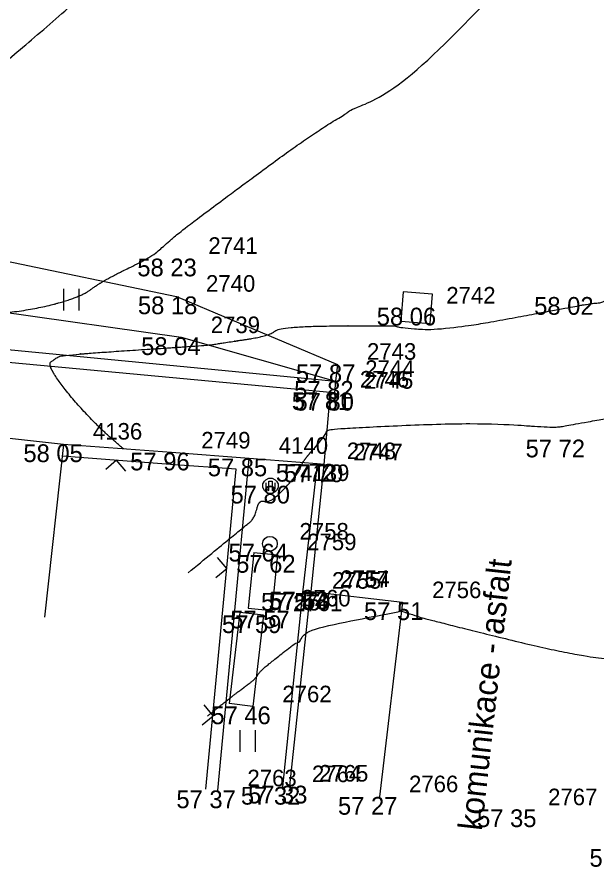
# Model space of a CAD drawing. Extents: x -704017 to -701500, y -1008977 to -1008450.
# Drawn here: x -702511.97 to -702502.17, y -1008779.72 to -1008765.36 of the extents above; entities that cross this region are included whole.
import ezdxf

# ---------------------------------------------------------------- set-up
doc = ezdxf.new("R2010")
doc.units = 0
for name, color, linetype in [('Z_body', 7, 'Continuous'), ('Z_body_cisla', 7, 'Continuous'), ('Z_body_vysky', 7, 'Continuous'), ('Z_budovy', 7, 'Continuous'), ('Z_chodnik', 7, 'Continuous'), ('Z_komunikace', 7, 'Continuous'), ('Z_obruby', 7, 'Continuous'), ('Z_oploceni', 7, 'Continuous'), ('Z_popis', 7, 'Continuous'), ('Z_rozhrani_ploch', 7, 'Continuous'), ('Z_site_znaky_nerozlisene', 7, 'Continuous'), ('Z_site_znaky_pilire', 7, 'Continuous'), ('Z_sloupy', 7, 'Continuous'), ('Z_teren_hrany_paty', 7, 'Continuous'), ('Z_vrstevnice_hlavni', 7, 'Continuous'), ('Z_vrstevnice_vedlejsi', 7, 'Continuous')]:
    doc.layers.add(name, color=color, linetype=linetype)

# ---------------------------------------------------------------- blocks, each defined once
blk = doc.blocks.new('POINT_DISPLAY')
blk.add_line((0, 0), (0, 0))
blk = doc.blocks.new('Z212')
for p, q in [((-0.17, 0.17), (0, 0)), ((0, 0), (0.17, 0.17))]:
    blk.add_line(p, q)
blk = doc.blocks.new('Z306')
for p, q in [((-0.13, 0.17), (-0.13, -0.2)), ((0.13, 0.17), (0.13, -0.2))]:
    blk.add_line(p, q)
blk = doc.blocks.new('Z601')
for p, q in [((-0.13, 0.03), (-0.1, 0.08)), ((-0.13, -0.03), (-0.13, 0.03)), ((-0.1, 0.08), (-0.08, 0.1)), ((-0.08, 0.1), (-0.03, 0.13)), ((-0.08, 0.05), (-0.08, -0.05)), ((-0.03, 0.13), (0.03, 0.13)), ((-0.03, -0.08), (-0.03, 0.08)), ((-0.03, 0.08), (0.03, 0.08)), ((0.03, 0.13), (0.08, 0.1)), ((0.03, 0.08), (0.03, -0.08)), ((0.08, 0.1), (0.1, 0.08)), ((0.08, -0.05), (0.08, 0.05)), ((0.1, 0.08), (0.13, 0.03)), ((0.13, 0.03), (0.13, -0.03)), ((-0.1, -0.08), (-0.13, -0.03)), ((-0.08, -0.1), (-0.1, -0.08)), ((-0.08, -0.05), (-0.03, -0.08)), ((-0.03, -0.13), (-0.08, -0.1)), ((0.03, -0.13), (-0.03, -0.13)), ((0.03, -0.08), (0.08, -0.05)), ((0.08, -0.1), (0.03, -0.13)), ((0.1, -0.08), (0.08, -0.1)), ((0.13, -0.03), (0.1, -0.08))]:
    blk.add_line(p, q)
blk = doc.blocks.new('Z15')
blk.add_circle((0, 0), 0.125)
blk = doc.blocks.new('Z608')
for p, q in [((0.25, 0.25), (-0.25, 0.25)), ((-0.25, 0.25), (-0.25, -0.25)), ((0.25, -0.25), (0.25, 0.25)), ((-0.25, -0.25), (0.25, -0.25))]:
    blk.add_line(p, q)

msp = doc.modelspace()

# ---------------------------------------------------------------- linework, layer by layer
at = {"layer": 'Z_budovy'}
for q in [(-702521.22, -1008771.47), (-702511.51, -1008775.5)]:
    msp.add_line((-702511.19, -1008772.58), q, dxfattribs=at)
at = {"layer": 'Z_chodnik'}
for p, q in [((-702513.76, -1008771.04), (-702506.68, -1008771.7)), ((-702506.9, -1008772.91), (-702508.05, -1008772.82)), ((-702506.79, -1008772.92), (-702506.9, -1008772.91))]:
    msp.add_line(p, q, dxfattribs=at)
at = {"layer": 'Z_komunikace'}
for p, q in [((-702513.59, -1008769.18), (-702509.28, -1008770.08)), ((-702509.28, -1008770.08), (-702506.56, -1008771.23)), ((-702506.56, -1008771.23), (-702506.59, -1008771.51)), ((-702506.59, -1008771.51), (-702506.61, -1008771.71)), ((-702506.68, -1008771.7), (-702506.79, -1008772.92)), ((-702506.61, -1008771.71), (-702506.68, -1008771.7)), ((-702506.79, -1008772.92), (-702507.01, -1008775.07)), ((-702507.01, -1008775.07), (-702505.46, -1008775.25)), ((-702505.46, -1008775.25), (-702505.85, -1008778.54))]:
    msp.add_line(p, q, dxfattribs=at)
at = {"layer": 'Z_obruby'}
for p, q in [((-702506.9, -1008772.91), (-702507.15, -1008775.09)), ((-702507.15, -1008775.09), (-702507.49, -1008778.37))]:
    msp.add_line(p, q, dxfattribs=at)
at = {"layer": 'Z_oploceni'}
for p, q in [((-702509.36, -1008772.72), (-702511.19, -1008772.58)), ((-702509.38, -1008772.92), (-702511.21, -1008772.78)), ((-702508.05, -1008772.82), (-702509.36, -1008772.72)), ((-702508.58, -1008778.43), (-702508.05, -1008772.82)), ((-702508.27, -1008773), (-702509.38, -1008772.92)), ((-702508.78, -1008778.41), (-702508.27, -1008773))]:
    msp.add_line(p, q, dxfattribs=at)
at = {"layer": 'Z_rozhrani_ploch'}
for p, q in [((-702513.76, -1008770.82), (-702506.59, -1008771.51)), ((-702507.02, -1008775.08), (-702507.37, -1008778.35)), ((-702507.02, -1008775.08), (-702507.01, -1008775.07))]:
    msp.add_line(p, q, dxfattribs=at)
at = {"layer": 'Z_site_znaky_pilire'}
for p, q in [((-702507.97, -1008774.41), (-702508.07, -1008775.35)), ((-702507.97, -1008774.41), (-702507.57, -1008774.45)), ((-702507.57, -1008774.45), (-702507.67, -1008775.39)), ((-702508.21, -1008775.42), (-702508.39, -1008776.96)), ((-702507.81, -1008775.47), (-702508.21, -1008775.42)), ((-702508.07, -1008775.35), (-702507.67, -1008775.39)), ((-702507.81, -1008775.47), (-702507.99, -1008777.01)), ((-702507.99, -1008777.01), (-702508.39, -1008776.96))]:
    msp.add_line(p, q, dxfattribs=at)
at = {"layer": 'Z_teren_hrany_paty'}
for p, q in [((-702513.5, -1008770.16), (-702509.2, -1008770.77)), ((-702509.2, -1008770.77), (-702506.59, -1008771.51))]:
    msp.add_line(p, q, dxfattribs=at)
at = {"layer": 'Z_vrstevnice_hlavni'}
for points in [[(-702534.597, -1008770.295), (-702534.448, -1008769.819), (-702534.826, -1008769.079), (-702534.909, -1008769.013), (-702535.136, -1008768.866), (-702531.758, -1008768.82), (-702529.231, -1008768.623), (-702527.5, -1008767.78), (-702523.893, -1008762.637), (-702523.353, -1008761.453), (-702522.917, -1008761.139), (-702520.245, -1008760.465), (-702519.05, -1008760.126), (-702517.563, -1008759.324), (-702516.36, -1008758.61), (-702515.627, -1008758.156), (-702515.438, -1008758.043), (-702513.225, -1008757.789), (-702511.155, -1008757.467), (-702509.023, -1008756.634), (-702507.215, -1008755.859), (-702507.12, -1008756.013), (-702506.973, -1008756.243), (-702506.557, -1008756.728), (-702506.345, -1008756.967), (-702505.288, -1008756.628), (-702504.948, -1008756.552), (-702504.756, -1008756.512), (-702504.52, -1008756.504), (-702500.611, -1008755.707)], [(-702510.173, -1008772.658), (-702510.714, -1008772.203), (-702511.484, -1008771.252), (-702511.319, -1008771.123), (-702511.199, -1008771.066), (-702508.725, -1008770.905), (-702508.579, -1008770.878), (-702507.701, -1008770.748), (-702507.528, -1008770.584), (-702505.643, -1008770.573), (-702505.563, -1008770.58), (-702505.541, -1008770.602), (-702504.772, -1008770.664), (-702502.568, -1008770.251), (-702502.295, -1008770.203), (-702501.897, -1008770.153), (-702498.702, -1008767.51), (-702496.853, -1008766.543), (-702495.43, -1008763.78), (-702492.386, -1008764.068), (-702489.794, -1008763.372), (-702489.696, -1008762.885)]]:
    msp.add_open_spline(points, degree=2, dxfattribs=at)
at = {"layer": 'Z_vrstevnice_vedlejsi'}
for points in [[(-702542.639, -1008769.714), (-702542.838, -1008769.212), (-702543.3, -1008768.491), (-702543.501, -1008768.378), (-702543.675, -1008768.267), (-702538.225, -1008768.28), (-702537.788, -1008768.224), (-702535.654, -1008768.195), (-702534.789, -1008768.127), (-702534.197, -1008767.839), (-702533.683, -1008767.256), (-702532.12, -1008765.699), (-702530.977, -1008764.328), (-702529.537, -1008761.735), (-702529.344, -1008761.026), (-702528.112, -1008760.74), (-702527.553, -1008760.132), (-702526.574, -1008759.427), (-702524.856, -1008758.993), (-702518.697, -1008758.854), (-702517.272, -1008757.84), (-702516.604, -1008756.952), (-702516.37, -1008756.589), (-702515.705, -1008756.233), (-702514.833, -1008755.724), (-702514.694, -1008755.618), (-702514.255, -1008755.522), (-702514.093, -1008755.47), (-702511.525, -1008755.071), (-702508.88, -1008754.038), (-702508.745, -1008753.995), (-702508.587, -1008753.97), (-702508.468, -1008753.928), (-702508.329, -1008753.854), (-702508.071, -1008753.863), (-702507.8, -1008754.437), (-702507.62, -1008754.728), (-702507.494, -1008754.926), (-702506.879, -1008754.827), (-702506, -1008754.776), (-702505.231, -1008754.636), (-702504.301, -1008754.446), (-702502.103, -1008754.372), (-702501.156, -1008754.179)], [(-702527.65, -1008770.9), (-702527.477, -1008769.653), (-702527.591, -1008769.52), (-702527.584, -1008769.441), (-702526.34, -1008769.36), (-702524.379, -1008769.182), (-702523.319, -1008769.181), (-702523.033, -1008769.141), (-702522.94, -1008768.96), (-702521.504, -1008768.383), (-702518.953, -1008764.338), (-702517.722, -1008763.86), (-702516.766, -1008763.33), (-702515.569, -1008761.869), (-702514.283, -1008761.177), (-702513.795, -1008761.077), (-702510.968, -1008759.888), (-702510.864, -1008759.877), (-702510.785, -1008759.864), (-702510.703, -1008759.832), (-702510.591, -1008759.784), (-702505.853, -1008757.953), (-702505.749, -1008758.075), (-702505.58, -1008758.265), (-702505.098, -1008758.697), (-702504.876, -1008758.883), (-702504.005, -1008758.519), (-702503.482, -1008758.333), (-702502.394, -1008758.065), (-702500.844, -1008757.777), (-702499.343, -1008757.118)], [(-702521.002, -1008771.494), (-702521.042, -1008771.46), (-702522.229, -1008770.186), (-702522.16, -1008770.12), (-702522.147, -1008769.98), (-702520.295, -1008769.812), (-702517.025, -1008769.809), (-702516.144, -1008769.686), (-702515.857, -1008769.127), (-702515.509, -1008768.987), (-702514.89, -1008768.006), (-702514.592, -1008767.89), (-702513.436, -1008767.249), (-702512.578, -1008766.462), (-702510.5, -1008764.7), (-702509.235, -1008763.065), (-702508.298, -1008762.872), (-702507.222, -1008762.42), (-702504.01, -1008760.05), (-702502.592, -1008761.081), (-702502.082, -1008760.79), (-702501.174, -1008760.378), (-702499.613, -1008759.927), (-702499.089, -1008759.845), (-702498.071, -1008759.493), (-702497.733, -1008759.375), (-702496.916, -1008759.016)], [(-702515.551, -1008772.097), (-702516.602, -1008771.204), (-702517.065, -1008770.707), (-702516.91, -1008770.558), (-702516.905, -1008770.505), (-702516.211, -1008770.442), (-702513.61, -1008770.439), (-702512.022, -1008770.37), (-702510.921, -1008770.111), (-702510.537, -1008769.818), (-702509.698, -1008769.413), (-702509.487, -1008769.219), (-702509.091, -1008768.884), (-702506.45, -1008766.935), (-702505.364, -1008766.536), (-702501.609, -1008762.469), (-702501.239, -1008762.181), (-702501.08, -1008762.265), (-702500.959, -1008762.33), (-702499.768, -1008762.768), (-702499.238, -1008762.582), (-702498.842, -1008762.527), (-702497.03, -1008762.51), (-702496.307, -1008762.053), (-702495.426, -1008761.674), (-702495.384, -1008761.634), (-702493.232, -1008761.347)], [(-702509.082, -1008774.752), (-702508.16, -1008773.989), (-702507.958, -1008773.839), (-702507.883, -1008773.506), (-702507.693, -1008773.586), (-702507.196, -1008773.049), (-702507.165, -1008772.889), (-702506.827, -1008772.507), (-702506.74, -1008772.365), (-702506.7, -1008772.315), (-702504.154, -1008772.204), (-702502.904, -1008772.303), (-702502.668, -1008772.259), (-702501.544, -1008772.061), (-702499.771, -1008771.993), (-702499.478, -1008771.685), (-702499.467, -1008771.638), (-702499.426, -1008771.559), (-702499.037, -1008771.486), (-702498.596, -1008771.389), (-702498.306, -1008771.275), (-702497.81, -1008771.23), (-702497.8, -1008771.38)], [(-702508.752, -1008777.172), (-702508.436, -1008776.911), (-702508.125, -1008776.681), (-702507.935, -1008776.536), (-702507.874, -1008776.421), (-702507.654, -1008776.242), (-702507.235, -1008775.91), (-702507.207, -1008775.94), (-702507.087, -1008775.703), (-702505.566, -1008775.422), (-702505.476, -1008775.387), (-702505.337, -1008775.469), (-702501.969, -1008776.294), (-702501.205, -1008776.114), (-702500.617, -1008776.187), (-702498.954, -1008775.799), (-702498.422, -1008775.522), (-702498.292, -1008775.125)]]:
    msp.add_open_spline(points, degree=2, dxfattribs=at)

# ---------------------------------------------------------------- block references
at = {"layer": 'Z_body'}
for p in [(-702509.24, -1008769.44), (-702509.28, -1008770.08), (-702502.56, -1008770.09), (-702505.22, -1008770.27), (-702509.2, -1008770.77), (-702506.56, -1008771.23), (-702506.59, -1008771.51), (-702506.68, -1008771.7), (-702506.61, -1008771.71), (-702502.68, -1008772.5), (-702511.19, -1008772.58), (-702509.36, -1008772.72), (-702508.05, -1008772.82), (-702506.9, -1008772.91), (-702506.79, -1008772.92), (-702507.69, -1008773.28), (-702507.7, -1008774.26), (-702507.57, -1008774.45), (-702507.15, -1008775.09), (-702507.02, -1008775.08), (-702507.01, -1008775.07), (-702505.46, -1008775.25), (-702507.67, -1008775.39), (-702507.81, -1008775.47), (-702507.99, -1008777.01), (-702508.58, -1008778.43), (-702507.49, -1008778.37), (-702507.37, -1008778.35), (-702505.85, -1008778.54), (-702503.5, -1008778.75)]:
    msp.add_blockref('POINT_DISPLAY', p, dxfattribs=at)
at = {"layer": 'Z_oploceni'}
for p, rotation in [((-702510.29, -1008772.85), 175.6), ((-702508.43, -1008774.68), 84.6), ((-702508.66, -1008777.17), 84.6)]:
    msp.add_blockref('Z212', p, dxfattribs=dict(at, rotation=rotation))
at = {"layer": 'Z_popis'}
for p in [(-702511.06, -1008770.12), (-702508.08, -1008777.58)]:
    msp.add_blockref('Z306', p, dxfattribs=at)
at = {"layer": 'Z_site_znaky_nerozlisene', "rotation": -4.4999999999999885}
msp.add_blockref('Z608', (-702505.22, -1008770.27), dxfattribs=at)
at = {"layer": 'Z_site_znaky_pilire'}
msp.add_blockref('Z15', (-702507.7, -1008774.26), dxfattribs=at)
at = {"layer": 'Z_sloupy'}
msp.add_blockref('Z601', (-702507.69, -1008773.28), dxfattribs=at)

# ---------------------------------------------------------------- texts
at = {"layer": 'Z_body_cisla'}
for s, p in [('2741', (-702508.74, -1008769.36)), ('2740', (-702508.78, -1008770)), ('2742', (-702504.72, -1008770.2)), ('2739', (-702508.7, -1008770.7)), ('2743', (-702506.06, -1008771.15)), ('2744', (-702506.09, -1008771.44)), ('2746', (-702506.18, -1008771.62)), ('2745', (-702506.11, -1008771.64)), ('4136', (-702510.69, -1008772.5)), ('2749', (-702508.86, -1008772.65)), ('4140', (-702507.55, -1008772.74)), ('2748', (-702506.4, -1008772.83)), ('2747', (-702506.29, -1008772.85)), ('4139', (-702507.19, -1008773.2)), ('2758', (-702507.2, -1008774.19)), ('2759', (-702507.07, -1008774.37)), ('2757', (-702506.52, -1008775)), ('2754', (-702506.51, -1008774.99)), ('2755', (-702506.65, -1008775.02)), ('2756', (-702504.96, -1008775.18)), ('2761', (-702507.31, -1008775.4)), ('2760', (-702507.17, -1008775.32)), ('2762', (-702507.49, -1008776.94)), ('2764', (-702506.99, -1008778.29)), ('2765', (-702506.87, -1008778.28)), ('2763', (-702508.08, -1008778.36)), ('2766', (-702505.35, -1008778.46)), ('2767', (-702503, -1008778.68))]:
    msp.add_text(s, height=0.28, dxfattribs=at).set_placement(p)
at = {"layer": 'Z_body_vysky'}
for s, p in [('58 23', (-702509.94, -1008769.74)), ('58 18', (-702509.93, -1008770.38)), ('58 02', (-702503.235, -1008770.39)), ('58 06', (-702505.895, -1008770.57)), ('58 04', (-702509.875, -1008771.07)), ('57 87', (-702507.26, -1008771.53)), ('57 82', (-702507.29, -1008771.81)), ('57 81', (-702507.33, -1008772)), ('57 80', (-702507.285, -1008772.01)), ('57 72', (-702503.38, -1008772.8)), ('58 05', (-702511.865, -1008772.88)), ('57 96', (-702510.06, -1008773.02)), ('57 85', (-702508.75, -1008773.12)), ('57 72', (-702507.6, -1008773.21)), ('57 70', (-702507.465, -1008773.22)), ('57 80', (-702508.365, -1008773.58)), ('57 64', (-702508.4, -1008774.56)), ('57 62', (-702508.27, -1008774.75)), ('57 56', (-702507.85, -1008775.39)), ('57 54', (-702507.72, -1008775.38)), ('57 53', (-702507.71, -1008775.37)), ('57 51', (-702506.11, -1008775.55)), ('57 57', (-702508.37, -1008775.69)), ('57 59', (-702508.51, -1008775.77)), ('57 46', (-702508.69, -1008777.31)), ('57 37', (-702509.28, -1008778.73)), ('57 32', (-702508.19, -1008778.67)), ('57 33', (-702508.07, -1008778.65)), ('57 27', (-702506.55, -1008778.84)), ('57 35', (-702504.2, -1008779.05)), ('57 27', (-702502.3, -1008779.72))]:
    msp.add_text(s, height=0.3, dxfattribs=at).set_placement(p)
at = {"layer": 'Z_popis'}
msp.add_text('komunikace - asfalt', height=0.4, rotation=83.7, dxfattribs=at).set_placement((-702504.12, -1008779.12))

doc.saveas('drawing.dxf')
